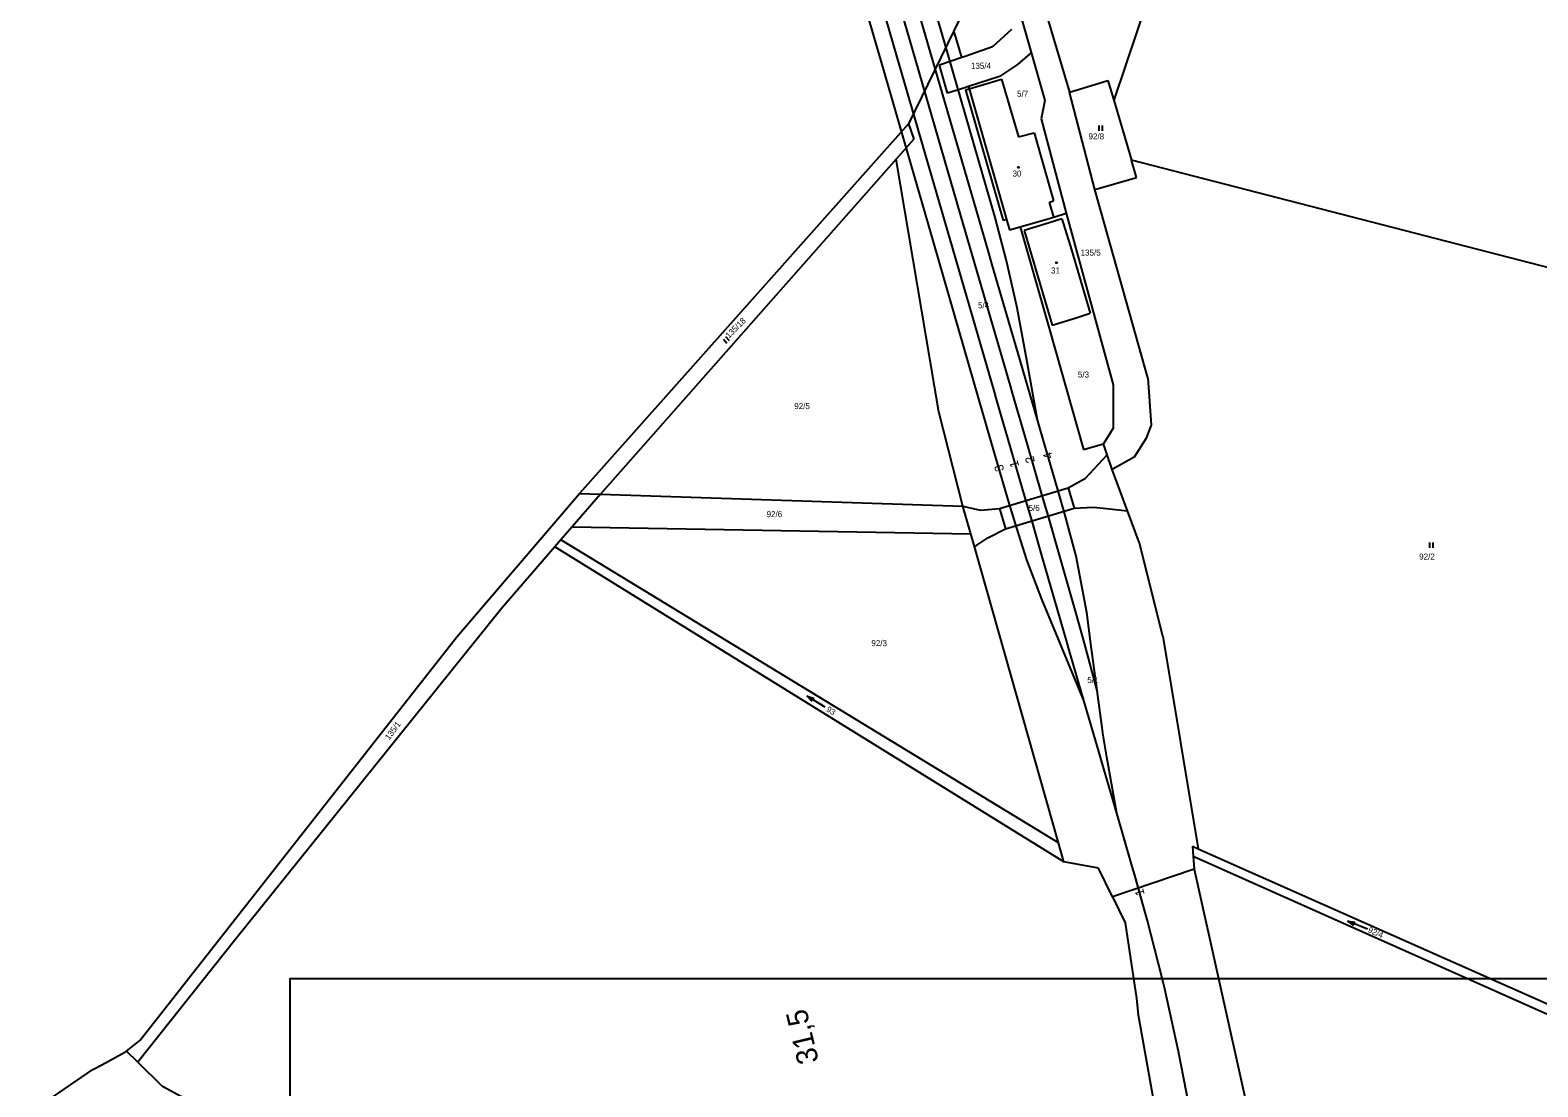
# Model space of a CAD drawing. Extents: x -752343 to -750336, y -1035826 to -1033329.
# Drawn here: x -752020.8 to -751593.9, y -1034170.4 to -1033871.2 of the extents above; entities that cross this region are included whole.
import ezdxf

# ---------------------------------------------------------------- set-up
doc = ezdxf.new("R2010")
doc.units = 0
for name, color, linetype in [('Default', 7, 'Continuous'), ('KN_HRANICE', 7, 'Continuous'), ('KN_KULTURY', 7, 'Continuous'), ('KN_PARCELY', 7, 'Continuous'), ('KN_SLUCKY', 7, 'Continuous'), ('LEGENDA', 7, 'Continuous'), ('Vrstva 1', 7, 'Continuous'), ('Vrstva 7', 7, 'Continuous')]:
    doc.layers.add(name, color=color, linetype=linetype)

# ---------------------------------------------------------------- blocks, each defined once
blk = doc.blocks.new('306')
at = {"layer": 'Default'}
for p, q in [((-0.5, 1.5), (-0.5, 0)), ((0.5, 0), (0.5, 1.5))]:
    blk.add_line(p, q, dxfattribs=at)
blk = doc.blocks.new('802')
at = {"layer": 'Default'}
blk.add_line((-3, 0), (3, 0), dxfattribs=at)
blk.add_lwpolyline([(1, 0.5), (3, 0), (1, -0.5)], dxfattribs=at)
blk = doc.blocks.new('402')
at = {"layer": 'Default'}
blk.add_lwpolyline([(0.09, 0.15), (0.18, 0), (0.09, -0.15), (-0.09, -0.15), (-0.18, 0), (-0.09, 0.15), (0.09, 0.15)], dxfattribs=at)

msp = doc.modelspace()

# ---------------------------------------------------------------- linework, layer by layer
at = {"layer": 'KN_HRANICE'}
for p, q in [((-751674.33, -1033773.12), (-751714, -1033891.06)), ((-751755.6, -1033863.97), (-751759.23, -1033871.39)), ((-751740.99, -1033865.03), (-751737.37, -1033877.6)), ((-751759.23, -1033871.39), (-751772.1, -1033897.72)), ((-751742.93, -1033871.04), (-751748.35, -1033875.98)), ((-751732.54, -1033868.49), (-751726.47, -1033888.81)), ((-751756.97, -1033879.02), (-751763.29, -1033881.13)), ((-751756.09, -1033878.73), (-751756.97, -1033879.02)), ((-751748.35, -1033875.98), (-751756.09, -1033878.73)), ((-751737.82, -1033877.99), (-751741.23, -1033880.94)), ((-751737.37, -1033877.6), (-751737.82, -1033877.99)), ((-751737.37, -1033877.6), (-751733.48, -1033891.19)), ((-751761.06, -1033889.12), (-751763.29, -1033881.13)), ((-751746.31, -1033884.36), (-751755.12, -1033887.2)), ((-751741.23, -1033880.94), (-751746.31, -1033884.36)), ((-751756.41, -1033887.62), (-751761.06, -1033889.12)), ((-751755.12, -1033887.2), (-751756.41, -1033887.62)), ((-751755.96, -1033888.09), (-751754.96, -1033887.81)), ((-751755.96, -1033888.09), (-751745.29, -1033925.15)), ((-751755.12, -1033887.2), (-751754.96, -1033887.81)), ((-751754.96, -1033887.81), (-751745.73, -1033885.12)), ((-751745.73, -1033885.12), (-751740.96, -1033901.39)), ((-751726.47, -1033888.81), (-751723.64, -1033887.9)), ((-751723.64, -1033887.9), (-751715.65, -1033885.47)), ((-751715.65, -1033885.47), (-751714, -1033891.06)), ((-751733.48, -1033891.19), (-751734.54, -1033896.35)), ((-751719.38, -1033916.32), (-751726.47, -1033888.81)), ((-751714, -1033891.06), (-751709, -1033908.01)), ((-751734.54, -1033896.35), (-751727.45, -1033923.08)), ((-751772.1, -1033897.72), (-751865.22, -1034002.43)), ((-751772.1, -1033897.72), (-751770.62, -1033902.06)), ((-751740.96, -1033901.39), (-751736.49, -1033900.33)), ((-751736.49, -1033900.33), (-751731.03, -1033919.59)), ((-751770.62, -1033902.06), (-751775.63, -1033907.74)), ((-751775.63, -1033907.74), (-751859.34, -1034002.62)), ((-751763.47, -1033979.26), (-751775.63, -1033907.74)), ((-751532.72, -1033953.48), (-751709, -1033908.01)), ((-751707.53, -1033912.99), (-751709, -1033908.01)), ((-751719.38, -1033916.32), (-751707.53, -1033912.99)), ((-751704.33, -1033969.64), (-751719.38, -1033916.32)), ((-751732.17, -1033919.91), (-751731.03, -1033919.59)), ((-751730.93, -1033924.18), (-751732.17, -1033919.91)), ((-751744.37, -1033924.89), (-751745.29, -1033925.15)), ((-751744.37, -1033924.89), (-751743.54, -1033927.8)), ((-751743.54, -1033927.8), (-751740.48, -1033926.92)), ((-751740.48, -1033926.92), (-751732.9, -1033924.75)), ((-751740.48, -1033926.92), (-751732.35, -1033955.36)), ((-751732.52, -1033925.84), (-751739.33, -1033928)), ((-751732.9, -1033924.75), (-751730.93, -1033924.18)), ((-751728.66, -1033924.7), (-751732.52, -1033925.84)), ((-751730.93, -1033924.18), (-751727.45, -1033923.08)), ((-751727.45, -1033923.08), (-751714.12, -1033971.65)), ((-751739.33, -1033928), (-751731.42, -1033954.79)), ((-751731.42, -1033954.79), (-751724.63, -1033952.67)), ((-751724.63, -1033952.67), (-751720.63, -1033951.41)), ((-751732.35, -1033955.36), (-751722.54, -1033989.94)), ((-751704.33, -1033969.64), (-751703.42, -1033983.08)), ((-751714.12, -1033971.65), (-751714.19, -1033983.94)), ((-751756.67, -1034005.98), (-751763.47, -1033979.26)), ((-751714.19, -1033983.94), (-751716.92, -1033988.33)), ((-751703.42, -1033983.08), (-751704.9, -1033986.94)), ((-751722.54, -1033989.94), (-751716.92, -1033988.33)), ((-751715.84, -1033991.47), (-751716.92, -1033988.33)), ((-751704.9, -1033986.94), (-751708.2, -1033992.17)), ((-751719.54, -1033995.41), (-751715.84, -1033991.47)), ((-751714.42, -1033995.62), (-751715.84, -1033991.47)), ((-751708.2, -1033992.17), (-751714.42, -1033995.62)), ((-751726.86, -1034000.83), (-751722, -1033998.05)), ((-751722, -1033998.05), (-751719.54, -1033995.41)), ((-751710.08, -1034007.36), (-751714.42, -1033995.62)), ((-751900.01, -1034043.01), (-751865.22, -1034002.43)), ((-751859.34, -1034002.62), (-751867.34, -1034011.88)), ((-751865.22, -1034002.43), (-751859.34, -1034002.62)), ((-751859.34, -1034002.62), (-751756.67, -1034005.98)), ((-751746.34, -1034006.65), (-751726.86, -1034000.83)), ((-751756.67, -1034005.98), (-751755.53, -1034006.28)), ((-751754.45, -1034013.82), (-751756.67, -1034005.98)), ((-751755.53, -1034006.28), (-751751.75, -1034007.11)), ((-751751.75, -1034007.11), (-751746.34, -1034006.65)), ((-751744.65, -1034012.41), (-751725.17, -1034006.61)), ((-751725.17, -1034006.61), (-751719.71, -1034006.3)), ((-751719.71, -1034006.3), (-751716.02, -1034006.71)), ((-751716.02, -1034006.71), (-751710.08, -1034007.36)), ((-751706.71, -1034016.5), (-751710.08, -1034007.36)), ((-751867.34, -1034011.88), (-751870.54, -1034015.58)), ((-751867.34, -1034011.88), (-751754.45, -1034013.82)), ((-751749.65, -1034014.95), (-751744.65, -1034012.41)), ((-751870.54, -1034015.58), (-751872.23, -1034017.53)), ((-751729.63, -1034101.32), (-751870.54, -1034015.58)), ((-751753.41, -1034017.47), (-751754.45, -1034013.82)), ((-751752.74, -1034017.03), (-751749.65, -1034014.95)), ((-751700.05, -1034042.8), (-751706.71, -1034016.5)), ((-751872.23, -1034017.53), (-751887.27, -1034034.92)), ((-751728.11, -1034106.69), (-751872.23, -1034017.53)), ((-751753.41, -1034017.47), (-751752.74, -1034017.03)), ((-751729.63, -1034101.32), (-751753.41, -1034017.47)), ((-751887.27, -1034034.92), (-751962.8, -1034128.91)), ((-751989.68, -1034157.31), (-751900.01, -1034043.01)), ((-751700.05, -1034042.8), (-751690.1, -1034103.01)), ((-751728.11, -1034106.69), (-751729.63, -1034101.32)), ((-751691.65, -1034102.32), (-751691.51, -1034105.14)), ((-751691.65, -1034102.32), (-751690.1, -1034103.01)), ((-751691.51, -1034105.14), (-751577.59, -1034155.94)), ((-751691.51, -1034105.14), (-751691.23, -1034108.8)), ((-751690.1, -1034103.01), (-751576.97, -1034153.3)), ((-751718.34, -1034108.48), (-751728.11, -1034106.69)), ((-751714.32, -1034116.59), (-751718.34, -1034108.48)), ((-751691.23, -1034108.8), (-751714.32, -1034116.59)), ((-751691.23, -1034108.8), (-751676.86, -1034173.28)), ((-751714.32, -1034116.59), (-751710.75, -1034123.97)), ((-751710.75, -1034123.97), (-751707.5, -1034145.45)), ((-751962.8, -1034128.91), (-751990.31, -1034163.44)), ((-751707.5, -1034145.45), (-751707.1, -1034150.04)), ((-751707.1, -1034150.04), (-751699.64, -1034191.17)), ((-751993.48, -1034160.36), (-751989.68, -1034157.31)), ((-752000.53, -1034164.18), (-751994.78, -1034161.06)), ((-751994.78, -1034161.06), (-751993.48, -1034160.36)), ((-751990.31, -1034163.44), (-751993.48, -1034160.36)), ((-752020.78, -1034177.67), (-752003.02, -1034165.53)), ((-752003.02, -1034165.53), (-752000.53, -1034164.18)), ((-751983.3, -1034170.28), (-751990.31, -1034163.44)), ((-751940.06, -1034193.83), (-751983.3, -1034170.28))]:
    msp.add_line(p, q, dxfattribs=at)
for points in [[(-751756.97, -1033879.02), (-751758.34, -1033874.4), (-751759.23, -1033871.39)], [(-751728.66, -1033924.7), (-751725.93, -1033933.46), (-751720.63, -1033951.41)]]:
    msp.add_lwpolyline(points, dxfattribs=at)
at = {"layer": 'KN_SLUCKY'}
for p, q in [((-751754.96, -1033887.81), (-751744.37, -1033924.89)), ((-751726.86, -1034000.83), (-751725.17, -1034006.61)), ((-751746.34, -1034006.65), (-751744.65, -1034012.41))]:
    msp.add_line(p, q, dxfattribs=at)
at = {"layer": 'LEGENDA'}
msp.add_lwpolyline([(-751353.18, -1034559.75), (-751947.18, -1034559.75), (-751947.18, -1034139.75), (-751353.18, -1034139.75)], close=True, dxfattribs=at)
at = {"layer": 'Vrstva 1'}
for p, q in [((-751743.1, -1033989.68), (-751747.25, -1033975.4)), ((-751738.45, -1033988.53), (-751742.63, -1033974.06)), ((-751715.93, -1034077.06), (-751717.03, -1034070.3))]:
    msp.add_line(p, q, dxfattribs=at)
for points in [[(-751747.7, -1033990.96), (-751752.23, -1033975.31), (-751766.26, -1033926.94), (-751779.77, -1033880.3), (-751794.62, -1033829.08), (-751808.74, -1033780.36), (-751822.83, -1033731.78), (-751836.05, -1033686.18), (-751847.86, -1033645.42), (-751861.7, -1033597.67), (-751876.18, -1033547.72), (-751888.67, -1033504.63), (-751900.66, -1033463.43), (-751906.4, -1033443.73), (-751912.15, -1033423.91), (-751917.69, -1033403.66), (-751919.57, -1033395.91), (-751922, -1033384.17), (-751924.19, -1033371.37)], [(-751747.25, -1033975.4), (-751747.77, -1033973.62), (-751761.05, -1033927.91), (-751775.46, -1033878.23), (-751789.94, -1033828.29), (-751803.8, -1033780.5), (-751818.3, -1033730.5), (-751831.4, -1033685.33), (-751843.36, -1033644.03), (-751857.18, -1033596.38), (-751871.7, -1033546.26), (-751884.52, -1033502.07), (-751896.51, -1033460.66), (-751904.76, -1033432.15), (-751912.03, -1033407.03)], [(-751742.63, -1033974.06), (-751743.25, -1033971.96), (-751756.5, -1033926.32), (-751770.85, -1033876.86), (-751785.4, -1033826.74), (-751799.32, -1033778.78), (-751813.72, -1033729.09), (-751826.88, -1033683.61), (-751838.83, -1033642.34), (-751852.51, -1033595.07), (-751867.05, -1033544.93), (-751874.95, -1033517.68), (-751883.31, -1033488.69), (-751888.73, -1033469.92), (-751892.18, -1033457.94), (-751895.7, -1033445.91)], [(-751748.37, -1033937.64), (-751749.35, -1033934.24), (-751752.08, -1033924.85), (-751766.48, -1033875.28), (-751780.94, -1033825.44), (-751794.79, -1033777.71), (-751809.23, -1033727.82), (-751822.32, -1033682.55), (-751834.31, -1033641.08), (-751848, -1033593.76), (-751862.53, -1033543.58), (-751870.21, -1033516.87), (-751874.49, -1033501.96), (-751877.86, -1033490.12), (-751881.3, -1033478.36)], [(-751744.43, -1033936.13), (-751747.53, -1033924.25), (-751761.89, -1033874.59), (-751776.58, -1033823.89), (-751790.24, -1033776.6), (-751804.68, -1033726.65), (-751817.84, -1033681.12), (-751829.8, -1033639.54), (-751843.42, -1033592.34), (-751857.99, -1033542.2), (-751866.58, -1033512.39), (-751871.08, -1033498.48), (-751874.93, -1033488.43), (-751879.76, -1033477.74)], [(-751733, -1033990.36), (-751733.37, -1033989.09), (-751735.57, -1033981.54), (-751740.37, -1033965.09), (-751740.58, -1033964.35), (-751748.37, -1033937.64)], [(-751733, -1033990.36), (-751733.37, -1033989.09), (-751735.57, -1033981.54), (-751738.62, -1033964.66), (-751741.32, -1033949.89), (-751744.06, -1033937.77), (-751744.43, -1033936.13)], [(-751718.04, -1034076.13), (-751718.23, -1034075.5), (-751722.42, -1034061.06), (-751728.38, -1034046.65), (-751729.23, -1034044.63), (-751734.33, -1034032.35), (-751738.56, -1034021.22), (-751741.45, -1034012.28), (-751743.58, -1034005.12), (-751747.7, -1033990.96)], [(-751718.04, -1034076.13), (-751718.23, -1034075.5), (-751722.42, -1034061.06), (-751726.76, -1034046.08), (-751727.16, -1034044.67), (-751734.31, -1034019.98), (-751736.92, -1034010.93), (-751739.03, -1034003.68), (-751743.1, -1033989.68)], [(-751722.17, -1034045.22), (-751722.64, -1034043.48), (-751724.59, -1034036.39), (-751729.68, -1034018.6), (-751732.31, -1034009.59), (-751734.46, -1034002.29), (-751738.45, -1033988.53)], [(-751717.03, -1034070.3), (-751717.14, -1034069.44), (-751718.65, -1034058.19), (-751720.43, -1034045), (-751721.63, -1034036.15), (-751724.6, -1034020.16), (-751727.81, -1034008.24), (-751729.89, -1034000.96), (-751733, -1033990.36)], [(-751717.03, -1034070.3), (-751717.14, -1034069.44), (-751718.65, -1034058.19), (-751722.17, -1034045.22)], [(-751708.76, -1034108.03), (-751708.95, -1034107.4), (-751713.15, -1034092.97), (-751717.49, -1034078.08), (-751718.04, -1034076.13)], [(-751708.76, -1034108.03), (-751708.95, -1034107.4), (-751713.15, -1034092.97), (-751715.93, -1034077.06)], [(-751704.41, -1034123.44), (-751706.68, -1034115.28), (-751708.06, -1034110.45), (-751708.76, -1034108.03)], [(-751692.67, -1034175.89), (-751695.63, -1034160.45), (-751699.64, -1034142.25), (-751700.26, -1034139.66), (-751704.41, -1034123.44)]]:
    msp.add_lwpolyline(points, dxfattribs=at)

# ---------------------------------------------------------------- block references
at = {"layer": 'KN_KULTURY'}
for name, p in [('306', (-751717.7, -1033899.74)), ('402', (-751740.95, -1033910.05)), ('402', (-751730.17, -1033937.06)), ('306', (-751624.08, -1034017.84))]:
    msp.add_blockref(name, p, dxfattribs=at)
for name, p, rotation in [('306', (-751823.13, -1033959.49), 42.284285), ('802', (-751798.21, -1034061.39), 148.338773), ('802', (-751644.89, -1034124.63), 157.620689)]:
    msp.add_blockref(name, p, dxfattribs=dict(at, rotation=rotation))

# ---------------------------------------------------------------- texts
at = {"layer": 'KN_PARCELY'}
for s, p in [('135/4', (-751754.42, -1033882.17)), ('5/7', (-751741.37, -1033890.09)), ('92/8', (-751721.13, -1033902.16)), ('30', (-751742.63, -1033912.68)), ('135/5', (-751723.38, -1033935.06)), ('31', (-751731.74, -1033940.13)), ('5/4', (-751752.42, -1033949.97)), ('5/3', (-751724.14, -1033969.59)), ('92/5', (-751804.44, -1033978.53)), ('92/6', (-751812.28, -1034009.12)), ('5/6', (-751738.1, -1034007.35)), ('92/2', (-751627.51, -1034021.13)), ('92/3', (-751782.61, -1034045.64)), ('5/1', (-751721.48, -1034056.06))]:
    msp.add_text(s, height=1.7, dxfattribs=at).set_placement(p)
for s, rotation, p in [('135/18', 45.034, (-751822.9, -1033958.6)), ('93', 328.133, (-751795.56, -1034063.98)), ('135/1', 53.342, (-751919.12, -1034072.33)), ('92/4', 336.555, (-751642.18, -1034126.61))]:
    msp.add_text(s, height=1.7, rotation=rotation, dxfattribs=at).set_placement(p)
at = {"layer": 'Vrstva 1'}
for s, rotation, p in [('4', 106.3986, (-751731.18, -1033992.24)), ('3', 106.2218, (-751744.97, -1033995.79)), ('1', 106.2082, (-751740.73, -1033994.64)), ('2', 106.152, (-751736.26, -1033993.39)), ('1', 106.0238, (-751705.19, -1034115.91))]:
    msp.add_text(s, height=2.5, rotation=rotation, dxfattribs=at).set_placement(p)
at = {"layer": 'Vrstva 7'}
msp.add_text('31,5', height=6, rotation=103.4304, dxfattribs=at).set_placement((-751797.45, -1034163.19))

doc.saveas('drawing.dxf')
